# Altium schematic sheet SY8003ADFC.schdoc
size 127 x 101 mm
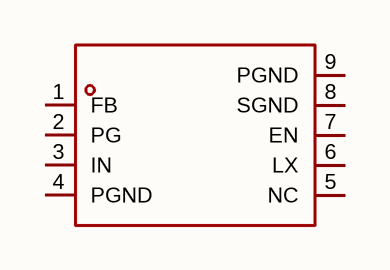
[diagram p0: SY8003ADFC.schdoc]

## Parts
U?  sy8003adfc  [DFN-8_L2.0-W2.0-P0.50-LS2.0-BL-EP]  (value not drawn)

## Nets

Not connected (* = marked no-connect by the designer): U? 1(FB) 2(PG) 3(IN) 4(PGND) 5(NC) 6(LX) 7(EN) 8(SGND) 9(PGND)

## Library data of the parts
U? = sy8003adfc: 功能类型:降压型;工作电压:2.7V~5.5V;输出电压:-;输出电流:3A;输出类型:可调;; Manufacturer: Silergy(矽力杰); AddInBom: yes; ModelId: ea9fe5daec6c437ca860910abaae89ca; ModelName: DFN-8_L2.0-W2.0-H0.8-P0.50; ModelTransform: 79.527,78.74,0,90,0,0,0,0,0; Function: 降压型; Output Current: 3A; Frequency - Switching: 1MHz; Synchronous Rectifier: 是; Number of Outputs: 1; Topology: 降压式; Quiescent Current: 55uA; Switch tube (built-in/external): 内置; Output Type: 可调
